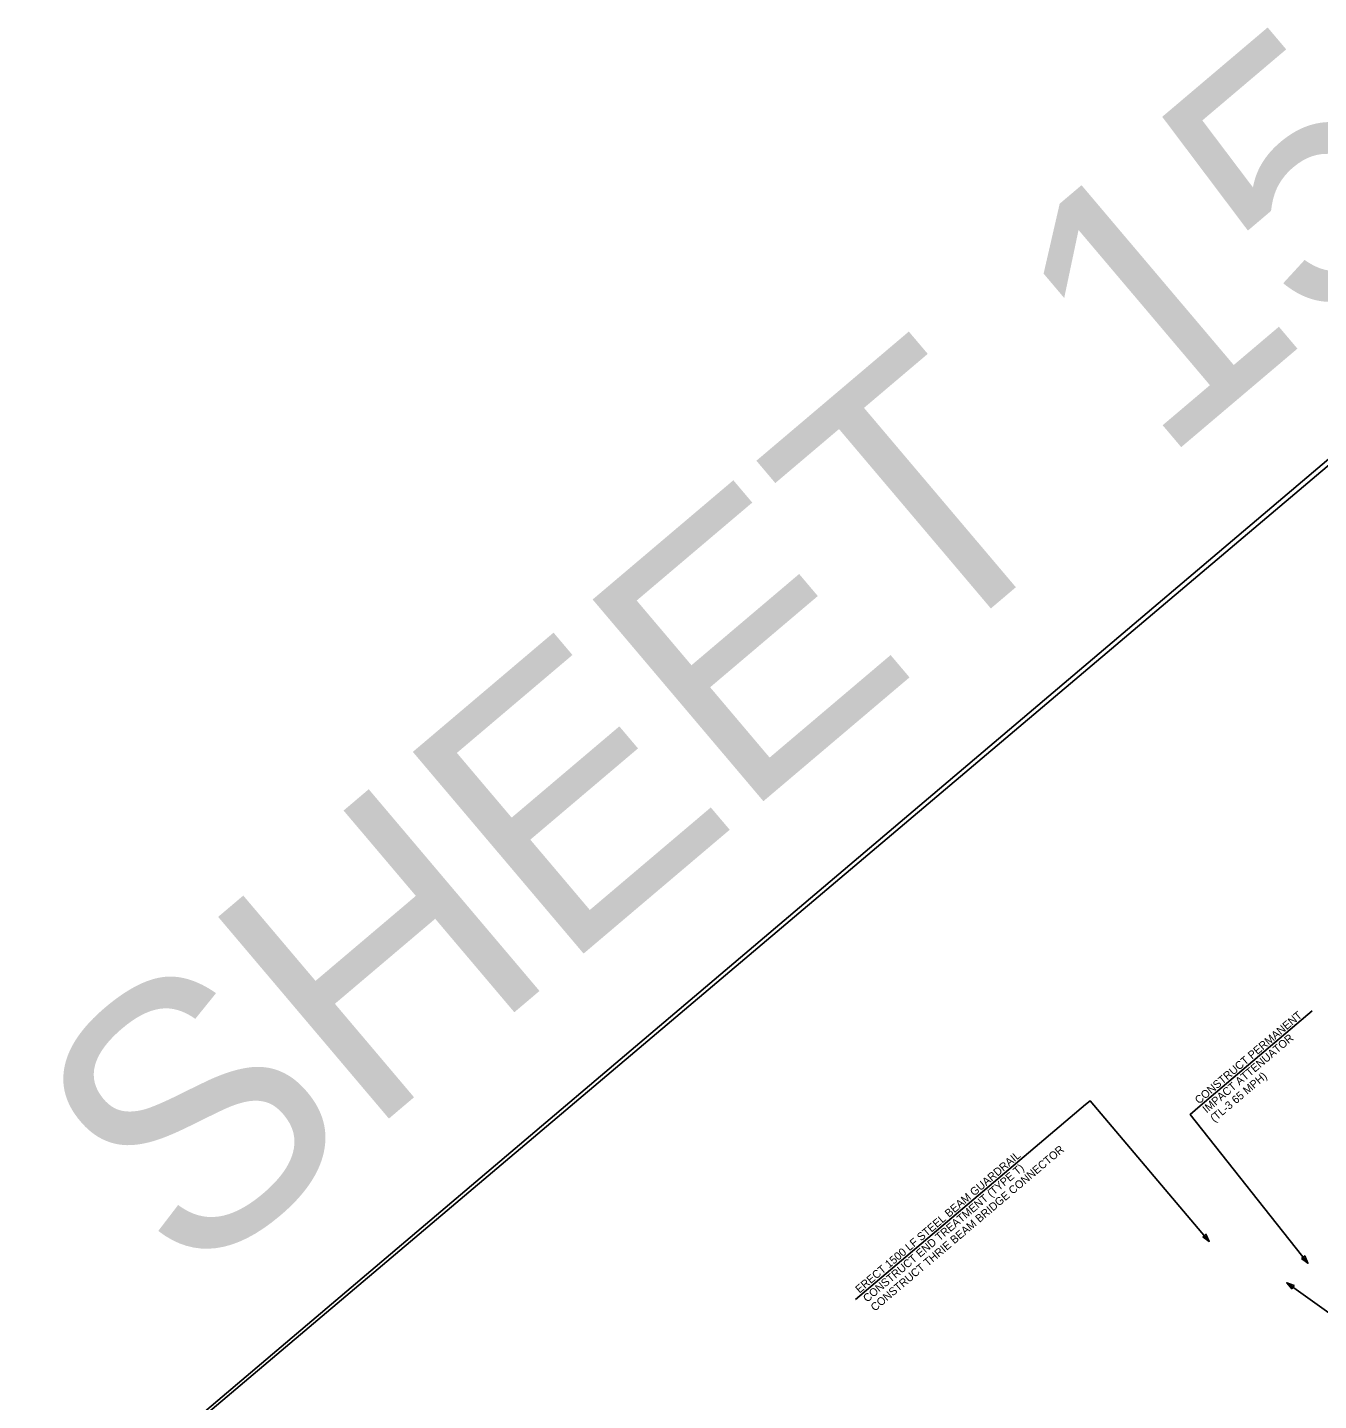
# Model space of a CAD drawing. Extents: x 1613433 to 1615331, y 1095338 to 1097615.
# Drawn here: x 1613433 to 1614410, y 1096576 to 1097615 of the extents above; entities that cross this region are included whole.
import ezdxf

# ---------------------------------------------------------------- set-up
doc = ezdxf.new("R2010")
doc.units = 0
for name, color, linetype in [('RD_EX_DR_Pipe', 7, 'Continuous'), ('RD_EX_GuardRail', 7, 'Continuous'), ('RD_HC_Data_Rel', 7, 'Continuous'), ('RD_PD_Final_TX', 7, 'Continuous'), ('RD_SHT_UT_TX_PREL', 7, 'Continuous')]:
    doc.layers.add(name, color=color, linetype=linetype)

msp = doc.modelspace()

# ---------------------------------------------------------------- linework, layer by layer
at = {"layer": 'RD_EX_DR_Pipe'}
msp.add_lwpolyline([(1613636.5, 1096424.5), (1613794.6, 1096211.8), (1613781.7, 1096202.2), (1613853.4, 1096105.7), (1613849.9, 1096103.1), (1613959.1, 1095956.1), (1614080.2, 1095752.7), (1615305.3, 1096791.9), (1615113.5, 1096968), (1614971.2, 1097080.2), (1614985.2, 1097098.2), (1614915.3, 1097153.9), (1614938.7, 1097183.2), (1614788.8, 1097308.4), (1614642.5, 1097430.7), (1614558.9, 1097359.3), (1614537.2, 1097384.7), (1613565.8, 1096563.6)], close=True, dxfattribs=at)
msp.add_lwpolyline([(1613636.5, 1096424.5), (1613794.6, 1096211.8), (1613781.7, 1096202.2), (1613853.4, 1096105.7), (1613849.9, 1096103.1), (1613959.1, 1095956.1), (1614080.2, 1095752.7), (1615305.3, 1096791.9), (1615113.5, 1096968), (1614971.2, 1097080.2), (1614985.2, 1097098.2), (1614915.3, 1097153.9), (1614938.7, 1097183.2), (1614788.8, 1097308.4), (1614642.5, 1097430.7), (1614558.9, 1097359.3), (1614537.2, 1097384.7), (1613565.8, 1096563.6)], close=True, dxfattribs=at)
at = {"layer": 'RD_EX_GuardRail'}
msp.add_lwpolyline([(1613432.5, 1096453.7), (1614710.7, 1097536.3), (1615328.9, 1096806.4), (1614050.7, 1095723.8)], close=True, dxfattribs=at)
at = {"layer": 'RD_HC_Data_Rel'}
for p, q in [((1614405.2, 1096870.5), (1614320.4, 1096798.6)), ((1614233.5, 1096799.6), (1614059.5, 1096652.2))]:
    msp.add_line(p, q, dxfattribs=at)
for points in [[(1614233.5, 1096799.6), (1614237, 1096802.5), (1614327.2, 1096696.1)], [(1614320.4, 1096798.6), (1614312.7, 1096792.1), (1614401.9, 1096679.6)]]:
    msp.add_lwpolyline(points, dxfattribs=at)
for points in [[(1614322.2, 1096699.6), (1614327.2, 1096696.1), (1614324.6, 1096701.6)], [(1614397.1, 1096683.1), (1614401.9, 1096679.6), (1614399.5, 1096685.1)]]:
    msp.add_lwpolyline(points, close=True, dxfattribs=at)
at = {"layer": 'RD_SHT_UT_TX_PREL'}
msp.add_lwpolyline([(1614503.1, 1096709), (1614421.3, 1096639.6), (1614385.8, 1096664.9)], dxfattribs=at)
msp.add_lwpolyline([(1614391.4, 1096662.8), (1614385.8, 1096664.9), (1614389.6, 1096660.3)], close=True, dxfattribs=at)

# ---------------------------------------------------------------- texts
at = {"layer": 'RD_HC_Data_Rel'}
for s, rotation, p in [('CONSTRUCT PERMANENT', 40.265, (1614319.4, 1096799.7)), ('IMPACT ATTENUATOR', 40.265, (1614325.2, 1096792.9)), ('(TL-3 65 MPH)', 40.265, (1614331, 1096786)), ('ERECT 1500 LF STEEL BEAM GUARDRAIL', 40.2667, (1614062.4, 1096656.6)), ('CONSTRUCT THRIE BEAM BRIDGE CONNECTOR', 40.2667, (1614074, 1096642.9)), ('CONSTRUCT END TREATMENT (TYPE T)', 40.2667, (1614068.2, 1096649.7))]:
    msp.add_text(s, height=6, rotation=rotation, dxfattribs=at).set_placement(p)
at = {"layer": 'RD_PD_Final_TX'}
msp.add_text('SHEET 15', height=200, rotation=40.265, dxfattribs=at).set_placement((1613553.3, 1096659.6))

doc.saveas('drawing.dxf')
